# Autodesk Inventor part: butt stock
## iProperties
Created: 2006-04
Part Number: butt stock
Document SubType Name: Modeling
Designer: Калинин
Author: Калинин
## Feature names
1. Вращение1 [Revolution]
2. Выдавливание1 [Extrusion]
3. Выдавливание2 [Extrusion]
4. Выдавливание3 [Extrusion]
5. Выдавливание4 [Extrusion]
6. Выдавливание5 [Extrusion]
7. Сопряжение1 [Fillet]
8. Отверстие1 [Hole]
9. Вращение2 [Revolution]
10. Выдавливание6 [Extrusion]
11. Выдавливание7 [Extrusion]
12. Выдавливание8 [Extrusion]
13. Сопряжение2 [Fillet]
14. Сопряжение3 [Fillet]
15. Сопряжение4 [Fillet]
16. Сопряжение7 [Fillet]
17. Выдавливание10 [Extrusion]
18. Сопряжение9 [Fillet]
19. Сопряжение10 [Fillet]
20. Сопряжение11 [Fillet]
21. Сопряжение12 [Fillet]
22. Сопряжение13 [Fillet]
23. Фаска1 [Chamfer]
24. Сопряжение14 [Fillet]
25. Сопряжение15 [Fillet]
26. Сопряжение16 [Fillet]
27. Сопряжение17 [Fillet]
28. Сопряжение18 [Fillet]
29. Сопряжение19 [Fillet]
30. Сопряжение20 [Fillet]
31. Сопряжение21 [Fillet]
